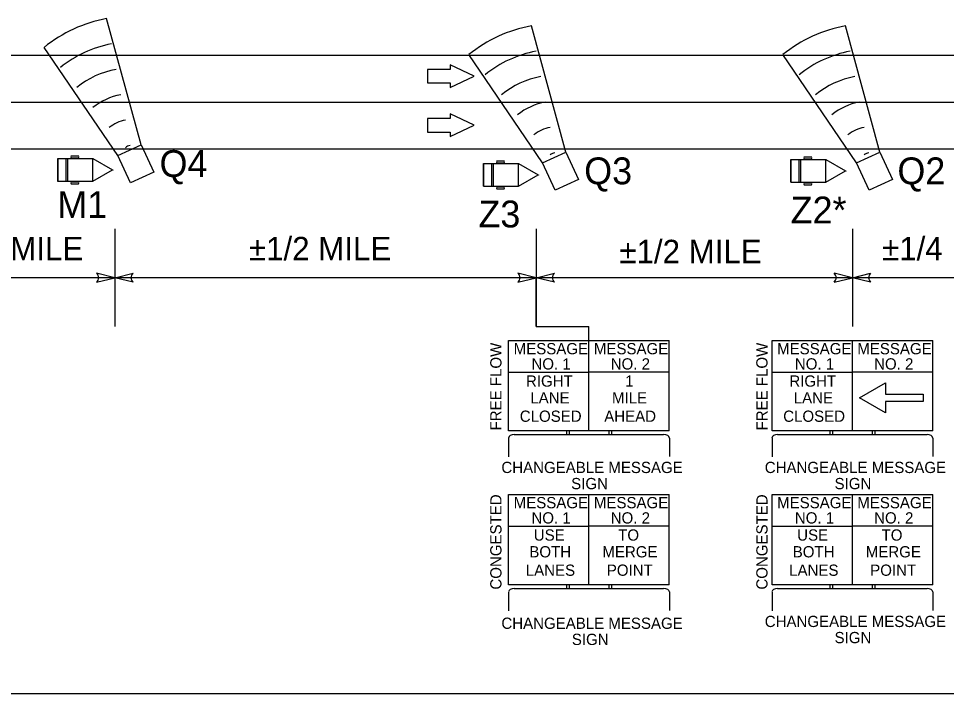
# Model space of a CAD drawing. Extents: x 1379436 to 1387057, y 792703 to 795604.
# Drawn here: x 1386121 to 1386649, y 795173 to 795558 of the extents above; entities that cross this region are included whole.
import ezdxf

# ---------------------------------------------------------------- set-up
doc = ezdxf.new("R2010")
doc.units = 0
for name, color, linetype in [('Black Area Fill Shapes', 7, 'Continuous'), ('Default', 7, 'Continuous'), ('DEV DIRECTION OF TRAFFIC FLOW ARROW CELL', 7, 'Continuous'), ('Prop Mkg Skp Wht', 7, 'Continuous'), ('Prop Mkg Solid White Lane Line', 7, 'Continuous'), ('Prop Mkg Solid Yellow Edge Line', 7, 'Continuous'), ('Text', 7, 'Continuous')]:
    doc.layers.add(name, color=color, linetype=linetype)

msp = doc.modelspace()

# ---------------------------------------------------------------- linework, layer by layer
at = {"layer": 'Black Area Fill Shapes'}
for points in [[(1386184.56, 795464.06), (1386177.4, 795479.61), (1386190.71, 795485.74), (1386197.87, 795470.2)], [(1386426.39, 795459.93), (1386419.23, 795475.47), (1386432.54, 795481.6), (1386439.7, 795466.06)], [(1386605.21, 795459.93), (1386598.05, 795475.47), (1386611.36, 795481.6), (1386618.52, 795466.06)], [(1386614.49, 795333.26), (1386599.81, 795341.73), (1386614.49, 795350.21), (1386614.49, 795343.86), (1386636, 795343.86), (1386636, 795339.6), (1386614.49, 795339.6)]]:
    msp.add_lwpolyline(points, close=True, dxfattribs=at)
at = {"layer": 'Default'}
for p, q in [((1386175.67, 795437.87), (1386175.67, 795382.35)), ((1386415.67, 795437.87), (1386415.67, 795382.35)), ((1386595.67, 795437.87), (1386595.67, 795382.35)), ((1386985.54, 795410.11), (1385695.67, 795410.11)), ((1386415.67, 795382.35), (1386415.67, 795410.11)), ((1386415.67, 795382.35), (1386445.7, 795382.35)), ((1386445.7, 795374.43), (1386445.7, 795382.35)), ((1386399.94, 795374.43), (1386491.45, 795374.43)), ((1386399.94, 795322.95), (1386399.94, 795374.43)), ((1386445.7, 795322.95), (1386445.7, 795374.43)), ((1386445.7, 795322.95), (1386445.7, 795374.43)), ((1386491.45, 795322.95), (1386491.45, 795374.43)), ((1386399.94, 795356.32), (1386445.7, 795356.32)), ((1386491.45, 795356.32), (1386445.7, 795356.32)), ((1386491.45, 795322.95), (1386399.94, 795322.95)), ((1386399.94, 795318.82), (1386399.94, 795308.2)), ((1386403.15, 795320.82), (1386488.23, 795320.82)), ((1386432.83, 795322.95), (1386432.83, 795320.82)), ((1386434.41, 795322.95), (1386434.41, 795320.82)), ((1386456.98, 795322.95), (1386456.98, 795320.82)), ((1386458.56, 795322.95), (1386458.56, 795320.82)), ((1386491.47, 795318.84), (1386491.47, 795308.22)), ((1386399.94, 795286.76), (1386491.45, 795286.76)), ((1386399.94, 795235.29), (1386399.94, 795286.76)), ((1386445.7, 795235.29), (1386445.7, 795286.76)), ((1386445.7, 795235.29), (1386445.7, 795286.76)), ((1386491.45, 795235.29), (1386491.45, 795286.76)), ((1386399.94, 795268.65), (1386445.7, 795268.65)), ((1386491.45, 795268.65), (1386445.7, 795268.65)), ((1386491.45, 795235.29), (1386399.94, 795235.29)), ((1386432.83, 795235.29), (1386432.83, 795233.16)), ((1386434.41, 795235.29), (1386434.41, 795233.16)), ((1386456.98, 795235.29), (1386456.98, 795233.16)), ((1386458.56, 795235.29), (1386458.56, 795233.16)), ((1386399.94, 795231.16), (1386399.94, 795220.54)), ((1386403.15, 795233.16), (1386488.23, 795233.16)), ((1386491.47, 795231.17), (1386491.47, 795220.55)), ((1384806.76, 795173.42), (1387056.77, 795173.42))]:
    msp.add_line(p, q, dxfattribs=at)
for centre, major_axis, start_param, end_param in [((1386403.16, 795318.84), (-3.24, 0), 4.712389, 6.283185), ((1386488.23, 795318.84), (3.24, 0), 0, 1.570796), ((1386403.16, 795231.17), (-3.24, 0), 4.712389, 6.283185), ((1386488.23, 795231.17), (3.24, 0), 0, 1.570796)]:
    msp.add_ellipse(centre, major_axis=major_axis, ratio=0.606795, start_param=start_param, end_param=end_param, dxfattribs=at)
at = {"layer": 'DEV DIRECTION OF TRAFFIC FLOW ARROW CELL'}
for p, q in [((1386366.62, 795531.32), (1386366.61, 795528.7)), ((1386380.37, 795524.83), (1386366.62, 795531.32)), ((1386353.84, 795528.71), (1386353.83, 795521)), ((1386366.61, 795528.7), (1386353.84, 795528.71)), ((1386366.61, 795518.36), (1386380.37, 795524.83)), ((1386353.83, 795521), (1386366.61, 795520.99)), ((1386366.61, 795520.99), (1386366.61, 795518.36)), ((1386366.62, 795503.37), (1386366.61, 795500.75)), ((1386380.37, 795496.88), (1386366.62, 795503.37)), ((1386353.84, 795500.76), (1386353.83, 795493.04)), ((1386366.61, 795500.75), (1386353.84, 795500.76)), ((1386353.83, 795493.04), (1386366.61, 795493.04)), ((1386366.61, 795490.41), (1386380.37, 795496.88)), ((1386366.61, 795493.04), (1386366.61, 795490.41))]:
    msp.add_line(p, q, dxfattribs=at)
at = {"layer": 'Prop Mkg Skp Wht'}
msp.add_line((1385896.18, 795510.08), (1386985.54, 795510.09), dxfattribs=at)
at = {"layer": 'Prop Mkg Solid White Lane Line'}
for p, q in [((1385896.18, 795483.46), (1386985.54, 795483.46)), ((1386143.27, 795477.9), (1386143.27, 795464.97)), ((1386143.27, 795477.89), (1386163.27, 795477.89)), ((1386143.27, 795464.96), (1386143.27, 795477.89)), ((1386147.95, 795464.96), (1386147.95, 795477.89)), ((1386149.02, 795464.96), (1386149.02, 795477.89)), ((1386150.83, 795479.52), (1386154.95, 795479.52)), ((1386150.83, 795478.3), (1386154.95, 795478.3)), ((1386163.27, 795464.97), (1386163.27, 795477.89)), ((1386163.27, 795477.89), (1386174.46, 795471.43)), ((1386560.65, 795477.38), (1386560.65, 795464.45)), ((1386560.65, 795477.37), (1386580.64, 795477.37)), ((1386560.65, 795464.44), (1386560.65, 795477.37)), ((1386565.32, 795464.44), (1386565.32, 795477.37)), ((1386566.39, 795464.44), (1386566.39, 795477.37)), ((1386568.2, 795479), (1386572.33, 795479)), ((1386568.2, 795477.78), (1386572.33, 795477.78)), ((1386580.64, 795464.45), (1386580.64, 795477.37)), ((1386580.64, 795477.37), (1386591.83, 795470.91)), ((1386385.64, 795475.1), (1386385.64, 795462.17)), ((1386385.64, 795475.09), (1386405.64, 795475.09)), ((1386385.64, 795462.16), (1386385.64, 795475.09)), ((1386390.31, 795462.16), (1386390.31, 795475.09)), ((1386391.38, 795462.16), (1386391.38, 795475.09)), ((1386393.19, 795476.72), (1386397.32, 795476.72)), ((1386393.19, 795475.5), (1386397.32, 795475.5)), ((1386405.64, 795462.17), (1386405.64, 795475.09)), ((1386405.64, 795475.09), (1386416.82, 795468.63)), ((1386163.27, 795464.97), (1386174.46, 795471.43)), ((1386405.64, 795462.17), (1386416.82, 795468.63)), ((1386580.64, 795464.45), (1386591.83, 795470.91)), ((1386143.27, 795464.97), (1386163.27, 795464.97)), ((1386150.83, 795464.71), (1386154.95, 795464.71)), ((1386150.83, 795463.54), (1386154.95, 795463.54)), ((1386385.64, 795462.17), (1386405.64, 795462.17)), ((1386393.19, 795461.91), (1386397.32, 795461.91)), ((1386560.65, 795464.45), (1386580.64, 795464.45)), ((1386568.2, 795464.19), (1386572.33, 795464.19)), ((1386568.2, 795463.02), (1386572.33, 795463.02)), ((1386393.19, 795460.74), (1386397.32, 795460.74)), ((1386549.92, 795374.43), (1386641.43, 795374.43)), ((1386549.92, 795322.95), (1386549.92, 795374.43)), ((1386595.67, 795322.95), (1386595.67, 795374.43)), ((1386595.67, 795322.95), (1386595.67, 795374.43)), ((1386641.43, 795322.95), (1386641.43, 795374.43)), ((1386549.92, 795356.32), (1386595.67, 795356.32)), ((1386641.43, 795356.32), (1386595.67, 795356.32)), ((1386641.43, 795322.95), (1386549.92, 795322.95)), ((1386549.92, 795318.82), (1386549.92, 795308.2)), ((1386553.12, 795320.82), (1386638.21, 795320.82)), ((1386582.81, 795322.95), (1386582.81, 795320.82)), ((1386584.39, 795322.95), (1386584.39, 795320.82)), ((1386606.96, 795322.95), (1386606.96, 795320.82)), ((1386608.54, 795322.95), (1386608.54, 795320.82)), ((1386641.45, 795318.84), (1386641.45, 795308.22)), ((1386549.92, 795286.76), (1386641.43, 795286.76)), ((1386549.92, 795235.29), (1386549.92, 795286.76)), ((1386595.67, 795235.29), (1386595.67, 795286.76)), ((1386595.67, 795235.29), (1386595.67, 795286.76)), ((1386641.43, 795235.29), (1386641.43, 795286.76)), ((1386549.92, 795268.65), (1386595.67, 795268.65)), ((1386641.43, 795268.65), (1386595.67, 795268.65)), ((1386641.43, 795235.29), (1386549.92, 795235.29)), ((1386582.81, 795235.29), (1386582.81, 795233.16)), ((1386584.39, 795235.29), (1386584.39, 795233.16)), ((1386606.96, 795235.29), (1386606.96, 795233.16)), ((1386608.54, 795235.29), (1386608.54, 795233.16)), ((1386549.92, 795231.16), (1386549.92, 795220.54)), ((1386553.12, 795233.16), (1386638.21, 795233.16)), ((1386641.45, 795231.17), (1386641.45, 795220.55))]:
    msp.add_line(p, q, dxfattribs=at)
for points in [[(1386165.28, 795407.51), (1386175.67, 795410.11), (1386165.28, 795412.71)], [(1386165.28, 795407.51), (1386175.67, 795410.11), (1386165.28, 795412.71)], [(1386186.07, 795407.51), (1386175.67, 795410.11), (1386186.07, 795412.71)], [(1386186.07, 795407.51), (1386175.67, 795410.11), (1386186.07, 795412.71)], [(1386405.28, 795407.51), (1386415.67, 795410.11), (1386405.28, 795412.71)], [(1386405.28, 795407.51), (1386415.67, 795410.11), (1386405.28, 795412.71)], [(1386426.07, 795407.51), (1386415.67, 795410.11), (1386426.07, 795412.71)], [(1386426.07, 795407.51), (1386415.67, 795410.11), (1386426.07, 795412.71)], [(1386585.28, 795407.51), (1386595.67, 795410.11), (1386585.28, 795412.71)], [(1386585.28, 795407.51), (1386595.67, 795410.11), (1386585.28, 795412.71)], [(1386606.07, 795407.51), (1386595.67, 795410.11), (1386606.07, 795412.71)], [(1386606.07, 795407.51), (1386595.67, 795410.11), (1386606.07, 795412.71)]]:
    msp.add_lwpolyline(points, dxfattribs=at)
for centre in [(1386174.57, 795471.42), (1386416.93, 795468.61), (1386591.94, 795470.9)]:
    msp.add_circle(centre, 0.114, dxfattribs=at)
for centre, radius, start, end in [((1386151.58, 795478.88), 0.954, 142.0883, 217.9117), ((1386154.2, 795478.88), 0.954, 322.0883, 37.9117), ((1386568.95, 795478.36), 0.954, 142.0883, 217.9117), ((1386571.58, 795478.36), 0.954, 322.0883, 37.9117), ((1386393.94, 795476.08), 0.954, 142.0883, 217.9117), ((1386396.57, 795476.08), 0.954, 322.0883, 37.9117), ((1386151.58, 795464.13), 0.954, 142.0883, 217.9117), ((1386154.2, 795464.13), 0.954, 322.0883, 37.9117), ((1386393.94, 795461.33), 0.954, 142.0883, 217.9117), ((1386396.57, 795461.33), 0.954, 322.0883, 37.9117), ((1386568.95, 795463.61), 0.954, 142.0883, 217.9117), ((1386571.58, 795463.61), 0.954, 322.0883, 37.9117), ((1386162.99, 795410.11), 3.46, 311.3264, 48.6736), ((1386162.99, 795410.11), 3.46, 311.3264, 48.6736), ((1386188.35, 795410.11), 3.46, 131.3264, 228.6736), ((1386188.35, 795410.11), 3.46, 131.3264, 228.6736), ((1386402.99, 795410.11), 3.46, 311.3264, 48.6736), ((1386402.99, 795410.11), 3.46, 311.3264, 48.6736), ((1386428.35, 795410.11), 3.46, 131.3264, 228.6736), ((1386428.35, 795410.11), 3.46, 131.3264, 228.6736), ((1386582.99, 795410.11), 3.46, 311.3264, 48.6736), ((1386582.99, 795410.11), 3.46, 311.3264, 48.6736), ((1386608.35, 795410.11), 3.46, 131.3264, 228.6736), ((1386608.35, 795410.11), 3.46, 131.3264, 228.6736)]:
    msp.add_arc(centre, radius, start, end, dxfattribs=at)
for centre, major_axis, start_param, end_param in [((1386553.14, 795318.84), (-3.24, 0), 4.712389, 6.283185), ((1386638.21, 795318.84), (3.24, 0), 0, 1.570796), ((1386553.14, 795231.17), (-3.24, 0), 4.712389, 6.283185), ((1386638.21, 795231.17), (3.24, 0), 0, 1.570796)]:
    msp.add_ellipse(centre, major_axis=major_axis, ratio=0.606795, start_param=start_param, end_param=end_param, dxfattribs=at)
at = {"layer": 'Prop Mkg Solid Yellow Edge Line'}
msp.add_line((1385896.18, 795536.7), (1386985.54, 795536.7), dxfattribs=at)
at = {"layer": 'Text'}
for p, q in [((1386190.71, 795485.74), (1386171.07, 795557.63)), ((1386432.54, 795481.6), (1386412.9, 795553.5)), ((1386611.36, 795481.6), (1386591.72, 795553.5)), ((1386177.4, 795479.61), (1386135.5, 795541.24)), ((1386419.23, 795475.47), (1386377.33, 795537.11)), ((1386598.05, 795475.47), (1386556.15, 795537.11))]:
    msp.add_line(p, q, dxfattribs=at)
for centre, radius in [((1386185.51, 795479.51), 79.44), ((1386427.34, 795475.37), 79.44), ((1386606.16, 795475.37), 79.44), ((1386185.51, 795479.51), 64.74), ((1386427.34, 795475.37), 64.74), ((1386606.16, 795475.37), 64.74), ((1386185.51, 795479.51), 50.04), ((1386427.34, 795475.37), 50.04), ((1386606.16, 795475.37), 50.04), ((1386185.51, 795479.51), 35.34), ((1386427.34, 795475.37), 35.34), ((1386606.16, 795475.37), 35.34), ((1386185.51, 795479.51), 20.63), ((1386427.34, 795475.37), 20.63), ((1386606.16, 795475.37), 20.63), ((1386185.51, 795479.51), 5.93), ((1386427.34, 795475.37), 5.93), ((1386606.16, 795475.37), 5.93)]:
    msp.add_arc(centre, radius, 100.4731, 129.0092, dxfattribs=at)

# ---------------------------------------------------------------- texts
at = {"layer": 'Default'}
for s, p in [('FREE FLOW', (1386395.89, 795323.13)), ('CONGESTED', (1386395.89, 795232.53))]:
    msp.add_text(s, height=6.403, rotation=90, dxfattribs=at).set_placement(p)
for s, height, p in [('MESSAGE', 6.403, (1386402.83, 795366.5)), ('MESSAGE', 6.403, (1386448.5, 795366.5)), ('NO. 1', 6.403, (1386412.95, 795357.83)), ('NO. 2', 6.403, (1386458.08, 795357.83)), ('RIGHT', 6.403, (1386409.82, 795348.07)), ('1', 6.4, (1386466.32, 795348.07)), ('LANE', 6.403, (1386412.31, 795338.53)), ('MILE', 6.403, (1386458.8, 795338.53)), ('CLOSED', 6.403, (1386406.31, 795328.05)), ('AHEAD', 6.403, (1386454.39, 795328.05)), ('CHANGEABLE MESSAGE', 6.4025, (1386395.83, 795298.89)), ('SIGN', 6.403, (1386435.56, 795289.7)), ('MESSAGE', 6.403, (1386402.83, 795278.84)), ('MESSAGE', 6.403, (1386448.5, 795278.84)), ('NO. 1', 6.403, (1386412.95, 795270.16)), ('NO. 2', 6.403, (1386458.08, 795270.16)), ('USE', 6.403, (1386414.28, 795260.41)), ('TO', 6.403, (1386462.33, 795260.41)), ('BOTH', 6.403, (1386411.74, 795250.87)), ('MERGE', 6.403, (1386453.33, 795250.87)), ('LANES', 6.403, (1386409.73, 795240.39)), ('POINT', 6.403, (1386455.86, 795240.39)), ('CHANGEABLE MESSAGE', 6.4025, (1386395.83, 795210.18)), ('SIGN', 6.403, (1386435.94, 795200.99))]:
    msp.add_text(s, height=height, dxfattribs=at).set_placement(p)
at = {"layer": 'Prop Mkg Solid White Lane Line'}
for s, p in [('FREE FLOW', (1386547.38, 795323.13)), ('CONGESTED', (1386547.38, 795232.53))]:
    msp.add_text(s, height=6.403, rotation=90, dxfattribs=at).set_placement(p)
for s, height, p in [('MESSAGE', 6.403, (1386552.81, 795366.5)), ('MESSAGE', 6.403, (1386598.48, 795366.5)), ('NO. 1', 6.403, (1386562.93, 795357.83)), ('NO. 2', 6.403, (1386608.06, 795357.83)), ('RIGHT', 6.403, (1386559.79, 795348.07)), ('LANE', 6.403, (1386562.29, 795338.53)), ('CLOSED', 6.403, (1386556.29, 795328.05)), ('CHANGEABLE MESSAGE', 6.4025, (1386545.8, 795298.89)), ('SIGN', 6.403, (1386585.54, 795289.7)), ('MESSAGE', 6.403, (1386552.81, 795278.84)), ('MESSAGE', 6.403, (1386598.48, 795278.84)), ('NO. 1', 6.403, (1386562.93, 795270.16)), ('NO. 2', 6.403, (1386608.06, 795270.16)), ('USE', 6.403, (1386564.26, 795260.41)), ('TO', 6.403, (1386612.3, 795260.41)), ('BOTH', 6.403, (1386561.72, 795250.87)), ('MERGE', 6.403, (1386603.3, 795250.87)), ('LANES', 6.403, (1386559.7, 795240.39)), ('POINT', 6.403, (1386605.83, 795240.39)), ('CHANGEABLE MESSAGE', 6.4025, (1386545.8, 795211.22)), ('SIGN', 6.403, (1386585.54, 795202.03))]:
    msp.add_text(s, height=height, dxfattribs=at).set_placement(p)
at = {"layer": 'Text'}
for s, height, p in [('Q4', 15.29, (1386201.18, 795467.42)), ('Q3', 15.29, (1386442.99, 795463.28)), ('Q2', 15.29, (1386621.33, 795463.28)), ('M1', 15.29, (1386142.93, 795444.07)), ('Z2*', 15.29, (1386560.53, 795440.99)), ('Z3', 15.29, (1386382.76, 795438.71)), ('±1/4 MILE', 13.31, (1386076.74, 795420.03)), ('±1/2 MILE', 13.31, (1386252.1, 795420.03)), ('±1/2 MILE', 13.31, (1386463.02, 795418.37)), ('±1/4 MILE', 13.31, (1386612.6, 795420.03))]:
    msp.add_text(s, height=height, dxfattribs=at).set_placement(p)

doc.saveas('drawing.dxf')
